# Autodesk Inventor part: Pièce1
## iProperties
Shininess: 20.0
Angle Display Precision: 2
Document Length Units: 11269
Document Angle Units: 11279
Document Time Units: 11290
Document Mass Units: 11283
Document Length Units Precision: 3
Document Angle Units Precision: 2
Compacted: True
Created: 2009-07
Part Number: Pièce1
Material: Par défaut
Document SubType Name: Modélisation
Designer: EL
Density: 1 g/cm^3
Density: 0.0
Volumn: 0.0
Area: 0.0
PropertySet Name: Model Information
Control State: 0
Master: False
Checked Out: False
Author: EL
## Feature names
1. Extrusion1
2. Extrusion2
3. Extrusion3
4. Extrusion4
5. Extrusion5
6. Extrusion6
7. Extrusion8
8. Extrusion9
